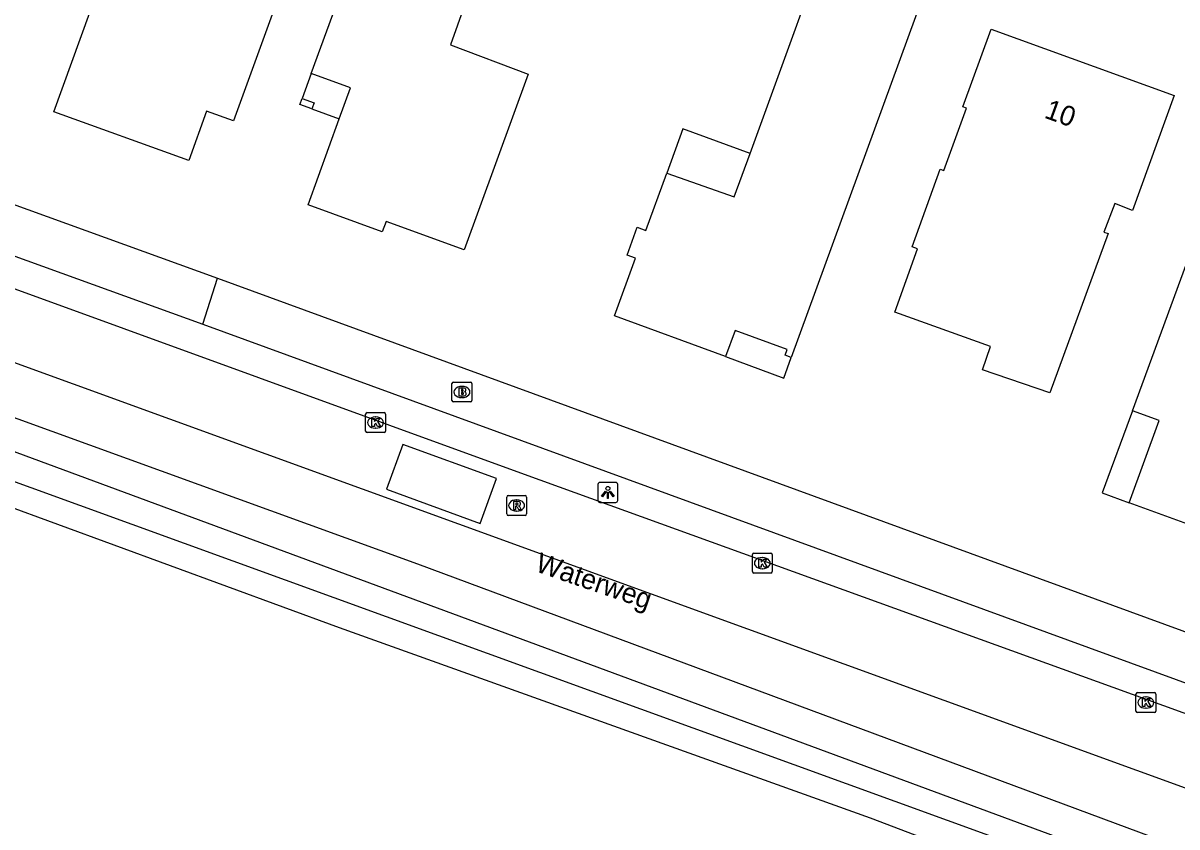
# Model space of a CAD drawing. Extents: x 155275 to 156263, y 382654 to 383635.
# Drawn here: x 155896.5 to 155954.5, y 383046.7 to 383087.1 of the extents above; entities that cross this region are included whole.
import ezdxf

# ---------------------------------------------------------------- set-up
doc = ezdxf.new("R2010")
doc.units = 0
for name, color, linetype in [('IMGEO_Berm_groen', 7, 'Continuous'), ('IMGEO_Brandkraan', 7, 'Continuous'), ('IMGEO_Kolk', 7, 'Continuous'), ('IMGEO_Lichtpunt', 7, 'Continuous'), ('IMGEO_Loofbos', 7, 'Continuous'), ('IMGEO_Openbare_ruimte_label', 7, 'Continuous'), ('IMGEO_Pand', 7, 'Continuous'), ('IMGEO_Pand_nummerreeks', 7, 'Continuous'), ('IMGEO_Pand_overbouw', 7, 'Continuous'), ('IMGEO_Rijbaan_lokaal_gesloten', 7, 'Continuous'), ('IMGEO_Rijbaan_lokaal_open', 7, 'Continuous'), ('IMGEO_Rioolput', 7, 'Continuous'), ('IMGEO_Voetpad_open', 7, 'Continuous'), ('IMGEO_Waterloop', 7, 'Continuous')]:
    doc.layers.add(name, color=color, linetype=linetype)

msp = doc.modelspace()

# ---------------------------------------------------------------- linework, layer by layer
at = {"layer": 'IMGEO_Berm_groen'}
msp.add_lwpolyline([(155977.107, 383037.846), (155976.899, 383037.927), (155963.443, 383042.424), (155916.345, 383059.928), (155861.438, 383079.847)], dxfattribs=at)
at = {"layer": 'IMGEO_Brandkraan'}
for p, q in [((155918.065, 383068.152), (155918.065, 383069.004)), ((155918.14, 383069.078), (155918.992, 383069.078)), ((155918.553, 383068.858), (155918.578, 383068.858)), ((155919.066, 383069.004), (155919.066, 383068.152)), ((155918.576, 383068.298), (155918.551, 383068.298)), ((155918.992, 383068.078), (155918.14, 383068.078))]:
    msp.add_line(p, q, dxfattribs=at)
for points in [[(155918.065, 383068.152), (155918.065, 383069.004)], [(155918.14, 383069.078), (155918.992, 383069.078)], [(155918.413, 383068.778), (155918.413, 383068.378), (155918.626, 383068.378)], [(155918.644, 383068.778), (155918.413, 383068.778)], [(155919.066, 383069.004), (155919.066, 383068.152)], [(155918.592, 383068.697), (155918.538, 383068.697), (155918.538, 383068.621)], [(155918.538, 383068.621), (155918.591, 383068.621)], [(155918.6, 383068.545), (155918.538, 383068.545), (155918.538, 383068.464)], [(155918.538, 383068.464), (155918.6, 383068.464)], [(155918.992, 383068.078), (155918.14, 383068.078)]]:
    msp.add_lwpolyline(points, dxfattribs=at)
for centre, radius, start, end in [((155918.142, 383069.002), 0.0765, 91.55205, 178.44795), ((155918.142, 383069.002), 0.0765, 91.55205, 178.44795), ((155918.648, 383068.633), 0.145, 59.4692, 91.53667), ((155918.673, 383068.68), 0.0922, 285.51372, 58.15012), ((155918.99, 383069.002), 0.0765, 1.55205, 88.44795), ((155918.99, 383069.002), 0.0765, 1.55205, 88.44795), ((155918.593, 383068.659), 0.0379, 267.82845, 90.93552), ((155918.601, 383068.504), 0.0404, 269.87594, 90.50774), ((155918.632, 383068.629), 0.251, 268.66757, 293.53466), ((155918.678, 383068.488), 0.105, 301.31148, 78.98903), ((155918.142, 383068.154), 0.0765, 181.55205, 268.44795), ((155918.142, 383068.154), 0.0765, 181.55205, 268.44795), ((155918.99, 383068.154), 0.0765, 271.55205, 358.44795), ((155918.99, 383068.154), 0.0765, 271.55205, 358.44795)]:
    msp.add_arc(centre, radius, start, end, dxfattribs=at)
for centre, major_axis, ratio, start_param, end_param in [((155918.552, 383068.578), (-0.387, 0.002), 0.722429, 4.712389, 7.853982), ((155918.577, 383068.578), (-0.39, 0.002), 0.717154, 1.570796, 4.712389)]:
    msp.add_ellipse(centre, major_axis=major_axis, ratio=ratio, start_param=start_param, end_param=end_param, dxfattribs=at)
at = {"layer": 'IMGEO_Kolk'}
for p, q in [((155913.727, 383066.618), (155913.727, 383067.47)), ((155913.802, 383067.544), (155914.654, 383067.544)), ((155914.215, 383067.324), (155914.24, 383067.324)), ((155914.728, 383067.47), (155914.728, 383066.618)), ((155914.654, 383066.544), (155913.802, 383066.544)), ((155914.238, 383066.764), (155914.213, 383066.764)), ((155933.145, 383059.559), (155933.145, 383060.411)), ((155933.22, 383060.485), (155934.072, 383060.485)), ((155933.633, 383060.265), (155933.658, 383060.265)), ((155934.146, 383060.411), (155934.146, 383059.559)), ((155934.072, 383059.485), (155933.22, 383059.485)), ((155933.656, 383059.705), (155933.631, 383059.705)), ((155952.402, 383052.56), (155952.402, 383053.412)), ((155952.477, 383053.486), (155953.329, 383053.486)), ((155952.89, 383053.266), (155952.915, 383053.266)), ((155953.403, 383053.412), (155953.403, 383052.56)), ((155952.913, 383052.706), (155952.888, 383052.706)), ((155953.329, 383052.486), (155952.477, 383052.486))]:
    msp.add_line(p, q, dxfattribs=at)
for points in [[(155913.727, 383066.618), (155913.727, 383067.47)], [(155913.802, 383067.544), (155914.654, 383067.544)], [(155914.048, 383067.244), (155914.171, 383067.244), (155914.171, 383067.093), (155914.301, 383067.244), (155914.465, 383067.244), (155914.319, 383067.093), (155914.472, 383066.844), (155914.32, 383066.844), (155914.235, 383067.008), (155914.171, 383066.941), (155914.171, 383066.844), (155914.048, 383066.844), (155914.048, 383067.244)], [(155914.728, 383067.47), (155914.728, 383066.618)], [(155914.654, 383066.544), (155913.802, 383066.544)], [(155933.145, 383059.559), (155933.145, 383060.411)], [(155933.22, 383060.485), (155934.072, 383060.485)], [(155933.466, 383060.185), (155933.589, 383060.185), (155933.589, 383060.034), (155933.719, 383060.185), (155933.883, 383060.185), (155933.737, 383060.034), (155933.89, 383059.785), (155933.738, 383059.785), (155933.653, 383059.949), (155933.589, 383059.882), (155933.589, 383059.785), (155933.466, 383059.785), (155933.466, 383060.185)], [(155934.146, 383060.411), (155934.146, 383059.559)], [(155934.072, 383059.485), (155933.22, 383059.485)], [(155952.402, 383052.56), (155952.402, 383053.412)], [(155952.477, 383053.486), (155953.329, 383053.486)], [(155952.723, 383053.186), (155952.846, 383053.186), (155952.846, 383053.035), (155952.976, 383053.186), (155953.14, 383053.186), (155952.994, 383053.035), (155953.147, 383052.786), (155952.995, 383052.786), (155952.91, 383052.95), (155952.846, 383052.883), (155952.846, 383052.786), (155952.723, 383052.786), (155952.723, 383053.186)], [(155953.403, 383053.412), (155953.403, 383052.56)], [(155953.329, 383052.486), (155952.477, 383052.486)]]:
    msp.add_lwpolyline(points, dxfattribs=at)
for centre, start, end in [((155913.804, 383067.468), 91.55205, 178.44795), ((155913.804, 383067.468), 91.55205, 178.44795), ((155914.652, 383067.468), 1.55205, 88.44795), ((155914.652, 383067.468), 1.55205, 88.44795), ((155913.804, 383066.62), 181.55205, 268.44795), ((155913.804, 383066.62), 181.55205, 268.44795), ((155914.652, 383066.62), 271.55205, 358.44795), ((155914.652, 383066.62), 271.55205, 358.44795), ((155933.222, 383060.409), 91.55205, 178.44795), ((155933.222, 383060.409), 91.55205, 178.44795), ((155934.07, 383060.409), 1.55205, 88.44795), ((155934.07, 383060.409), 1.55205, 88.44795), ((155933.222, 383059.561), 181.55205, 268.44795), ((155933.222, 383059.561), 181.55205, 268.44795), ((155934.07, 383059.561), 271.55205, 358.44795), ((155934.07, 383059.561), 271.55205, 358.44795), ((155952.479, 383053.41), 91.55205, 178.44795), ((155952.479, 383053.41), 91.55205, 178.44795), ((155953.327, 383053.41), 1.55205, 88.44795), ((155953.327, 383053.41), 1.55205, 88.44795), ((155952.479, 383052.562), 181.55205, 268.44795), ((155952.479, 383052.562), 181.55205, 268.44795), ((155953.327, 383052.562), 271.55205, 358.44795), ((155953.327, 383052.562), 271.55205, 358.44795)]:
    msp.add_arc(centre, 0.0765, start, end, dxfattribs=at)
for centre, major_axis, ratio, start_param, end_param in [((155914.214, 383067.044), (-0.387, 0.002), 0.722429, 4.712389, 7.853982), ((155914.239, 383067.044), (-0.39, 0.002), 0.717154, 1.570796, 4.712389), ((155933.632, 383059.985), (-0.387, 0.002), 0.722429, 4.712389, 7.853982), ((155933.657, 383059.985), (-0.39, 0.002), 0.717154, 1.570796, 4.712389), ((155952.889, 383052.986), (-0.387, 0.002), 0.722429, 4.712389, 7.853982), ((155952.914, 383052.986), (-0.39, 0.002), 0.717154, 1.570796, 4.712389)]:
    msp.add_ellipse(centre, major_axis=major_axis, ratio=ratio, start_param=start_param, end_param=end_param, dxfattribs=at)
at = {"layer": 'IMGEO_Lichtpunt'}
for p, q in [((155925.391, 383063.939), (155925.391, 383063.132)), ((155925.391, 383063.939), (155925.391, 383063.132)), ((155926.293, 383064.034), (155925.485, 383064.034)), ((155926.293, 383064.034), (155925.485, 383064.034)), ((155926.387, 383063.132), (155926.387, 383063.939)), ((155926.387, 383063.132), (155926.387, 383063.939)), ((155925.485, 383063.038), (155926.293, 383063.038)), ((155925.485, 383063.038), (155926.293, 383063.038))]:
    msp.add_line(p, q, dxfattribs=at)
for points in [[(155925.765, 383063.603), (155925.804, 383063.575), (155925.616, 383063.313), (155925.578, 383063.34), (155925.765, 383063.603)], [(155925.867, 383063.555), (155925.914, 383063.555), (155925.914, 383063.233), (155925.867, 383063.233), (155925.867, 383063.555)], [(155925.977, 383063.575), (155926.015, 383063.602), (155926.202, 383063.34), (155926.163, 383063.312), (155925.977, 383063.575)]]:
    msp.add_lwpolyline(points, dxfattribs=at)
msp.add_circle((155925.89, 383063.737), 0.0994, dxfattribs=at)
for centre, start, end in [((155925.485, 383063.939), 90, 180), ((155925.485, 383063.939), 90, 180), ((155926.293, 383063.939), 0, 90), ((155926.293, 383063.939), 0, 90), ((155925.485, 383063.132), 180, 270), ((155925.485, 383063.132), 180, 270), ((155926.293, 383063.132), 270, 0), ((155926.293, 383063.132), 270, 360)]:
    msp.add_arc(centre, 0.0946, start, end, dxfattribs=at)
at = {"layer": 'IMGEO_Loofbos'}
msp.add_lwpolyline([(155859.737, 383076.199), (155865.3, 383074.216), (155892.593, 383064.019), (155912.4, 383056.746), (155939.054, 383047.189), (155966.873, 383036.607), (155975.546, 383033.476)], dxfattribs=at)
at = {"layer": 'IMGEO_Pand'}
for points in [[(155914.89, 383103.668), (155907.09, 383082.193), (155905.745, 383082.68), (155904.847, 383080.197), (155898.076, 383082.648), (155901.693, 383092.641), (155905.196, 383091.37), (155905.639, 383092.588), (155907.97, 383091.748), (155909.165, 383095.155), (155906.905, 383096.018), (155907.31, 383097.173), (155906.079, 383097.621), (155909.057, 383105.798)], [(155919.288, 383096.704), (155917.266, 383091.137), (155917.105, 383091.192), (155916.272, 383088.866), (155918.699, 383087.979), (155917.998, 383086.014), (155921.891, 383084.543), (155918.68, 383075.713), (155914.755, 383077.135), (155914.559, 383076.625), (155910.851, 383077.978), (155912.408, 383082.29), (155912.972, 383083.851), (155911, 383084.573), (155915.893, 383097.946), (155919.288, 383096.704)], [(155943.454, 383093.254), (155935.094, 383070.315), (155934.792, 383070.427), (155934.893, 383070.708), (155932.279, 383071.669), (155931.802, 383070.364), (155926.226, 383072.4), (155927.283, 383075.301), (155926.862, 383075.457), (155927.365, 383076.853), (155927.796, 383076.692), (155928.846, 383079.561), (155932.237, 383078.379), (155933.03, 383080.557), (155937.805, 383093.684), (155935.693, 383094.477), (155936.22, 383095.894)], [(155954.327, 383083.469), (155952.235, 383077.697), (155951.337, 383078.037), (155950.796, 383076.608), (155951.009, 383076.535), (155948.075, 383068.537), (155944.698, 383069.695), (155945.1, 383070.867), (155940.299, 383072.588), (155941.437, 383075.764), (155941.164, 383075.863), (155942.582, 383079.773), (155942.759, 383079.708), (155943.895, 383082.835), (155943.716, 383082.9), (155945.14, 383086.799), (155954.327, 383083.469)], [(155911.141, 383083.095), (155911.031, 383082.794), (155910.43, 383083.014), (155910.54, 383083.314), (155911.141, 383083.095)], [(155957.564, 383082.179), (155961.052, 383080.896), (155958.829, 383074.834), (155961.398, 383073.894), (155960.461, 383071.355), (155961.279, 383071.068), (155963.618, 383070.247), (155961.363, 383064.149), (155958.903, 383065.085), (155957.407, 383061.069), (155952.055, 383063.021), (155953.56, 383067.143), (155952.221, 383067.635), (155957.564, 383082.179)]]:
    msp.add_lwpolyline(points, dxfattribs=at)
at = {"layer": 'IMGEO_Pand_overbouw'}
for points in [[(155911.031, 383082.794), (155912.408, 383082.29), (155912.972, 383083.851), (155911, 383084.573), (155910.54, 383083.314), (155911.141, 383083.095)], [(155928.846, 383079.561), (155932.237, 383078.379), (155933.03, 383080.557), (155929.647, 383081.787)], [(155935.094, 383070.315), (155934.792, 383070.427), (155934.893, 383070.708), (155932.279, 383071.669), (155931.802, 383070.364), (155934.728, 383069.281)], [(155952.221, 383067.635), (155950.707, 383063.513), (155952.055, 383063.021), (155953.56, 383067.143)]]:
    msp.add_lwpolyline(points, close=True, dxfattribs=at)
at = {"layer": 'IMGEO_Rijbaan_lokaal_gesloten'}
for points in [[(155861.375, 383086.397), (155921.687, 383064.46), (155968.257, 383047.604)], [(155966.958, 383044.307), (155860.181, 383083.103)]]:
    msp.add_lwpolyline(points, dxfattribs=at)
at = {"layer": 'IMGEO_Rijbaan_lokaal_open'}
msp.add_lwpolyline([(155919.48, 383061.975), (155920.303, 383064.242), (155915.601, 383065.95), (155914.78, 383063.704), (155919.48, 383061.975)], dxfattribs=at)
at = {"layer": 'IMGEO_Rioolput'}
for p, q in [((155920.811, 383062.453), (155920.811, 383063.305)), ((155920.886, 383063.379), (155921.738, 383063.379)), ((155921.299, 383063.159), (155921.324, 383063.159)), ((155921.812, 383063.305), (155921.812, 383062.453)), ((155921.738, 383062.379), (155920.886, 383062.379)), ((155921.322, 383062.599), (155921.297, 383062.599))]:
    msp.add_line(p, q, dxfattribs=at)
for points in [[(155920.811, 383062.453), (155920.811, 383063.305)], [(155920.886, 383063.379), (155921.738, 383063.379)], [(155921.4, 383063.077), (155921.148, 383063.079), (155921.148, 383062.679)], [(155921.326, 383062.998), (155921.272, 383062.998), (155921.272, 383062.917)], [(155921.812, 383063.305), (155921.812, 383062.453)], [(155921.738, 383062.379), (155920.886, 383062.379)], [(155921.148, 383062.679), (155921.272, 383062.679), (155921.272, 383062.841), (155921.283, 383062.841)], [(155921.272, 383062.917), (155921.324, 383062.917)], [(155921.33, 383062.812), (155921.401, 383062.679), (155921.541, 383062.679), (155921.476, 383062.805)]]:
    msp.add_lwpolyline(points, dxfattribs=at)
for centre, radius, start, end in [((155920.888, 383063.303), 0.0765, 91.55205, 178.44795), ((155920.888, 383063.303), 0.0765, 91.55205, 178.44795), ((155921.332, 383062.902), 0.0964, 77.00612, 93.18647), ((155921.346, 383062.959), 0.0378, 276.66336, 79.67722), ((155921.399, 383062.967), 0.109, 350.36119, 89.41601), ((155921.397, 383062.967), 0.112, 277.58423, 350.98172), ((155921.736, 383063.303), 0.0765, 1.55205, 88.44795), ((155921.736, 383063.303), 0.0765, 1.55205, 88.44795), ((155920.888, 383062.455), 0.0765, 181.55205, 268.44795), ((155920.888, 383062.455), 0.0765, 181.55205, 268.44795), ((155921.282, 383062.788), 0.0533, 26.02933, 88.69889), ((155921.308, 383063.106), 0.19, 274.7715, 282.96867), ((155921.381, 383062.752), 0.108, 29.51342, 73.79051), ((155921.736, 383062.455), 0.0765, 271.55205, 358.44795), ((155921.736, 383062.455), 0.0765, 271.55205, 358.44795)]:
    msp.add_arc(centre, radius, start, end, dxfattribs=at)
for centre, major_axis, ratio, start_param, end_param in [((155921.298, 383062.879), (-0.387, 0.002), 0.722429, 4.712389, 7.853982), ((155921.323, 383062.879), (-0.39, 0.002), 0.717154, 1.570796, 4.712389)]:
    msp.add_ellipse(centre, major_axis=major_axis, ratio=ratio, start_param=start_param, end_param=end_param, dxfattribs=at)
at = {"layer": 'IMGEO_Voetpad_open'}
for points in [[(155860.971, 383090.709), (155906.289, 383074.293)], [(155860.149, 383088.414), (155905.553, 383071.987)], [(155905.553, 383071.987), (155906.289, 383074.293)], [(155906.289, 383074.293), (155973.17, 383049.852), (155976.436, 383048.685)], [(155905.553, 383071.987), (155968.122, 383049.145), (155970.921, 383048.142), (155970.447, 383046.818)]]:
    msp.add_lwpolyline(points, dxfattribs=at)
at = {"layer": 'IMGEO_Waterloop'}
msp.add_lwpolyline([(155976.478, 383035.871), (155862.028, 383078.166), (155861.325, 383078.049), (155860.599, 383078.213), (155860.389, 383077.44), (155860.904, 383077.252), (155861.044, 383076.807), (155976.153, 383035.013), (155976.478, 383035.871)], dxfattribs=at)

# ---------------------------------------------------------------- texts
at = {"layer": 'IMGEO_Openbare_ruimte_label'}
msp.add_text('Waterweg', height=1, rotation=341.14816, dxfattribs=at).set_placement((155922.191, 383059.592))
at = {"layer": 'IMGEO_Pand_nummerreeks'}
msp.add_text('10', height=1, rotation=340.07674, dxfattribs=at).set_placement((155947.75, 383082.365))

doc.saveas('drawing.dxf')
